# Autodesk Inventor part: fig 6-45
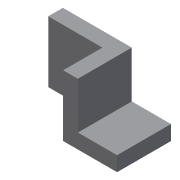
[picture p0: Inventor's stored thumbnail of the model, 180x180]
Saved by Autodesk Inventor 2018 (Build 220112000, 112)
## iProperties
Shininess: 77.0
Angle Display Precision: 2
Document Length Units: 11269
Document Angle Units: 11279
Document Time Units: 11290
Document Mass Units: 11283
Document Length Units Precision: 3
Document Angle Units Precision: 2
Created: 2001-12
Part Number: fig 6-45
Document SubType Name: Modeling
Designer: Renu Muthoo
Density: 1 g/cm^3
Material: Generic
Appearance: Default
Density: 0.0
Volumn: 0.0
Area: 0.0
PropertySet Name: Model Information
Control State: 0
Master: False
Checked Out: False
Author: Renu Muthoo
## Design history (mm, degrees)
node "Sketch1"
sketch "Sketch2"
  geometry: L1 (16.794, 27.142)-(16.794, -22.858); L2 (16.794, -22.858)-(-27.206, -22.858); L3 (-27.206, -22.858)-(-27.206, -10.858); L4 (-27.206, -10.858)-(4.794, -10.858); L5 (4.794, -10.858)-(4.794, 27.142); L6 (4.794, 27.142)-(16.794, 27.142)
  constraints: 12 end point, 4 parallel, 2 perpendicular, 1 vertical
  dimensions: "d0" = 44 distance of L1.end L2.end; "d1" = 50 distance of L1.start L1.end; "d2" = 12 distance of L2.end L3.end
extrude "Extrusion1" new body sketch "Sketch2" distance "d3" = 44; taper "d4" = 0 deg
sketch "Sketch4"
  geometry: L1 (-16.794, -27.142)-(-16.794, 22.858) reference; L2 (27.206, 22.858)-(27.206, 10.858) reference; L3 (-16.794, -27.142)-(-61.001, -27.142); L4 (-61.001, -27.142)-(-61.001, 22.858); L5 (-61.001, 22.858)-(-16.794, 22.858)
  constraints: 6 end point, 2 perpendicular, 1 parallel
extrude "Extrusion3" join sketch "Sketch4" distance "d13" = 12; taper "d14" = 0 deg
body "Solid1"
